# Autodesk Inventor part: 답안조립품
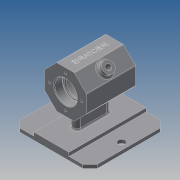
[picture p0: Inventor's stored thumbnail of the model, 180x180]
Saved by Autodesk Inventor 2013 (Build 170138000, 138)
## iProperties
Created: 2018-06
Part Number: 답안조립품
Material: Generic
Document SubType Name: Modeling
Designer: doa
Density: 1 g/cm^3
Author: doa
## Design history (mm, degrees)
sketch "스케치2"
  geometry: L1 (30, -12.426)-(12.426, -30); L2 (12.426, -30)-(-12.426, -30); L3 (-12.426, -30)-(-30, -12.426); L4 (-30, -12.426)-(-30, 12.426); L5 (-30, 12.426)-(-12.426, 30); L6 (-12.426, 30)-(12.426, 30); L7 (12.426, 30)-(30, 12.426); L8 (30, 12.426)-(30, -12.426); 2 further points
  constraints: 16 end point, 1 coincident, 1 vertical, 17 other
  dimensions: "d7" = 60 distance between parallel lines of L6 L2
extrude "돌출1" new body sketch "스케치2" stored distance "d8" = 70; taper "d9" = 0 deg
sketch "스케치3"
  geometry: L1 (0, 35)-(0, -40.032); L2 (30, -35)-(-30, -35) reference; L3 (-30, -35)-(-30, 35) reference; L4 (-30, 35)-(30, 35) reference; L5 (30, 35)-(30, -35) reference; L6 (16, 35)-(16, 23); L7 (16, 23)-(14, 23); L8 (14, 23)-(14, 20); L9 (14, 20)-(25, 20); L10 (25, 20)-(25, -20); L11 (25, -20)-(14, -20); L12 (14, -20)-(14, -23); L13 (14, -23)-(16, -23); L14 (16, -23)-(16, -35); L15 (0, -35)-(16, -35); L16 (16, 35)-(0, 35); L17 (0, 35)-(0, -35); 1 further point
  constraints: 26 end point, 7 parallel, 3 perpendicular, 3 point on line, 2 collinear, 1 midpoint, 1 vertical
  dimensions: "d10" = 12 distance of L6.start L6.end; "d12" = 32 diameter of L6 L1; "d13" = 50 diameter of L10 L1; "d14" = 3 distance of L7.end L8.end; "d15" = 3 distance of L11.end L12.end; "d16" = 12 distance of L13.end L14.end; "d17" = 28 diameter of L8 L1; "d18" = 32 diameter of L14 L1; "d19" = 28 diameter of L12 L1
revolve "회전1" sketch "스케치3" stored, may be unused: angle "d20" = 90 deg
node "작업 평면1"
sketch "스케치5"
  geometry: L1 (-55, 55)-(55, 55); L2 (55, 55)-(55, -55); L3 (55, -55)-(-55, -55); L4 (-55, -55)-(-55, 55); 1 further point
  constraints: 8 end point, 2 parallel, 1 horizontal, 1 perpendicular
  dimensions: "d22" = 110 distance between parallel lines of L2 L4; "d24" = 110 distance between parallel lines of L3 L1; "d25" = 55 horizontal distance of L1.end point (0, 0); "d26" = 55 horizontal distance of L1.end point (0, 0)
extrude "돌출2" join sketch "스케치5" distance "d27" = 5; taper "d28" = 0 deg
sketch "스케치6"
  geometry: L1 (55, -55)-(55, 55) reference; L2 (55, -55)-(-55, -55) reference; L3 (-55, -55)-(-55, 55) reference; L4 (-55, 55)-(55, 55) reference; L5 (55, 55)-(55, -55) reference; L6 (55, -55)-(-55, -55) reference; L7 (-55, -55)-(-55, 55) reference; L8 (-55, 55)-(55, 55) reference; L9 (55, 55)-(55, -55) reference; L10 (-45, 55)-(-55, 45); L11 (-55, 55)-(-45, 55); L12 (-55, 55)-(-55, 45); L13 (45, 55)-(55, 55); L14 (55, 55)-(55, 45); L15 (55, 45)-(45, 55); L16 (45, -55)-(55, -45); L17 (55, -45)-(55, -55); L18 (55, -55)-(45, -55); L19 (-55, -55)-(-55, -45); L20 (-55, -45)-(-45, -55); L21 (-45, -55)-(-55, -55); 1 further point
  constraints: 24 end point, 8 point on line, 4 collinear, 3 perpendicular
  dimensions: "d29" = 10 distance of L3.end L10.end; "d30" = 10 distance of L3.end L10.start; "d31" = 10 distance of L2.end L19.end; "d32" = 10 distance of L20.end L2.end; "d33" = 10 distance of L1.start L16.start; "d34" = 10 distance of L16.end L1.start; "d35" = 10 distance of L1.end L13.start
extrude "돌출3" cut sketch "스케치6" stored distance "d36" = 5; taper "d37" = 0 deg
sketch "스케치7"
  geometry: L1 (-55, 45)-(-55, -45) reference; L2 (-45, -55)-(45, -55) reference; L3 (55, -45)-(55, 45) reference; L4 (45, 55)-(-45, 55) reference; L5 (25, 55)-(-25, 55); L6 (-25, 55)-(-25, -55); L7 (-25, -55)-(25, -55); L8 (25, -55)-(25, 55); 1 further point
  constraints: 8 end point, 2 parallel, 2 point on line, 1 horizontal, 1 perpendicular
  dimensions: "d38" = 30 distance between parallel lines of L3 L8; "d39" = 30 distance between parallel lines of L1 L6
extrude "돌출4" join sketch "스케치7" distance "d40" = 5; taper "d41" = 0 deg
sketch "스케치8"
  geometry: L1 (-25, 55)-(-25, -55) reference; L2 (5, 19)-(5, -19); L3 (-5, -19)-(-5, 19); A1 r 5 centre (0, 19) between (5, 19) and (-5, 19); A2 r 5 centre (0, -19) between (-5, -19) and (5, -19); 1 further point
  constraints: 4 end point, 4 point on circle, 3 tangent, 2 centre point, 2 vertical alignment, 1 equal radius, 1 parallel
  dimensions: "d42" = 10 diameter of A1; "d44" = 38 distance of A2.centre A1.centre; "d45" = 19 distance of point (0, 0) A1.centre
extrude "돌출5" join sketch "스케치8" stored distance "d46" = 5; taper "d47" = 0 deg
sketch "스케치9"
  geometry: L1 (0, 0)-(0, 70) reference; L2 (-24.853, 70)-(0, 70) reference; L3 (-24.853, 70)-(-24.853, 0) reference; L4 (0, 0)-(-24.853, 0) reference; L5 (-24.853, 35)-(0, 35); L6 (-12.426, 70)-(-12.426, 0); C1 r 8 at (-12.426, 35); 1 further point
  constraints: 4 end point, 4 midpoint, 1 centre point, 1 coincident
  dimensions: "d51" = 16 diameter of C1
extrude "돌출6" join sketch "스케치9" distance "d53" = 7; taper "d54" = 0 deg
sketch "스케치10"
  geometry: C1 r 8 at (0, 0) reference; C2 r 4 at (0, 0)
  constraints: 1 centre point, 1 coincident
  dimensions: "d55" = 8 diameter of C2
extrude "돌출7" cut sketch "스케치10" stored distance "d57" = 7; taper "d58" = 0 deg
fillet "모깎기1" dims "d59" = 1
sketch "스케치11"
  geometry: C1 r 16 at (0, 0) reference; A1 r 23 centre (0, 0) between (-23, 0) and (23, 0); 2 further points
  constraints: 4 point on circle, 2 horizontal alignment, 2 vertical alignment, 1 centre point, 1 coincident
  dimensions: "d60" = 46 diameter of A1
hole "구멍1" sketch "스케치11" at (-23, 0), (23, 0), (0, 23), (0, -23) diameter "d62" = 3.242; stored, may be unused: countersink angle "d66" = 90 deg, drill point angle "d68" = 118 deg; dims "d63" = 8, "d64" = 4, "d65" = 2, "d67" = 10
sketch "스케치12"
  geometry: L1 (-25, 55)-(-45, 55) reference; L2 (-55, 45)-(-55, -45) reference; C1 r 5 at (-45, 0); 1 further point
  constraints: 1 centre point
  dimensions: "d69" = 55 distance from line of C1.centre L1; "d70" = 10 distance from line of L2 C1.centre; "d71" = 10 diameter of C1
extrude "돌출8" cut sketch "스케치12" stored distance "d72" = 7; taper "d73" = 0 deg
fillet "모깎기2" dims "d74" = 2
fillet "모깎기3" dims "d75" = 3
fillet "모깎기4" dims "d76" = 0.3
fillet "모깎기5" dims "d77" = 2
fillet "모깎기6" dims "d78" = 3
chamfer "모따기1" distance "d79" = 1; stored, may be unused: second distance "d80" = 2, angle "d81" = 45 deg
sketch "스케치13"
  geometry: L1 (-24.024, 70)-(0, 70) reference; L2 (0, 70)-(0, 0) reference; L3 (0, 0)-(-24.024, 0) reference; L4 (-24.024, 0)-(-24.024, 70) reference; L5 (-34.338, 29.122)-(-34.338, 40.878) reference; L6 (17.988, 0)-(17.988, 70) reference; L7 (17.695, 70)-(17.695, 0) reference; L8 (0.707, 70)-(17.695, 70) reference; 3 further points; 1 other entity
  constraints: 1 coincident, 2 other
feature "엠보싱1" sketch "스케치13" dims "d10" = 12, "d12" = 32, "d13" = 50, "d14" = 3, "d15" = 3, "d16" = 12, "d17" = 28, "d18" = 32, "d19" = 28, "d82" = 0.5, "d83" = 0
node "솔리드1"
mirror "대칭1"
mirror "대칭2"
node "절단 모서리 투영1"
node "절단 모서리 투영2"
node "절단 모서리 투영3"
node "절단 모서리 투영4"
other parameters: "d21" = 62
